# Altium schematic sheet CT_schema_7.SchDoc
size 226 x 144 mm
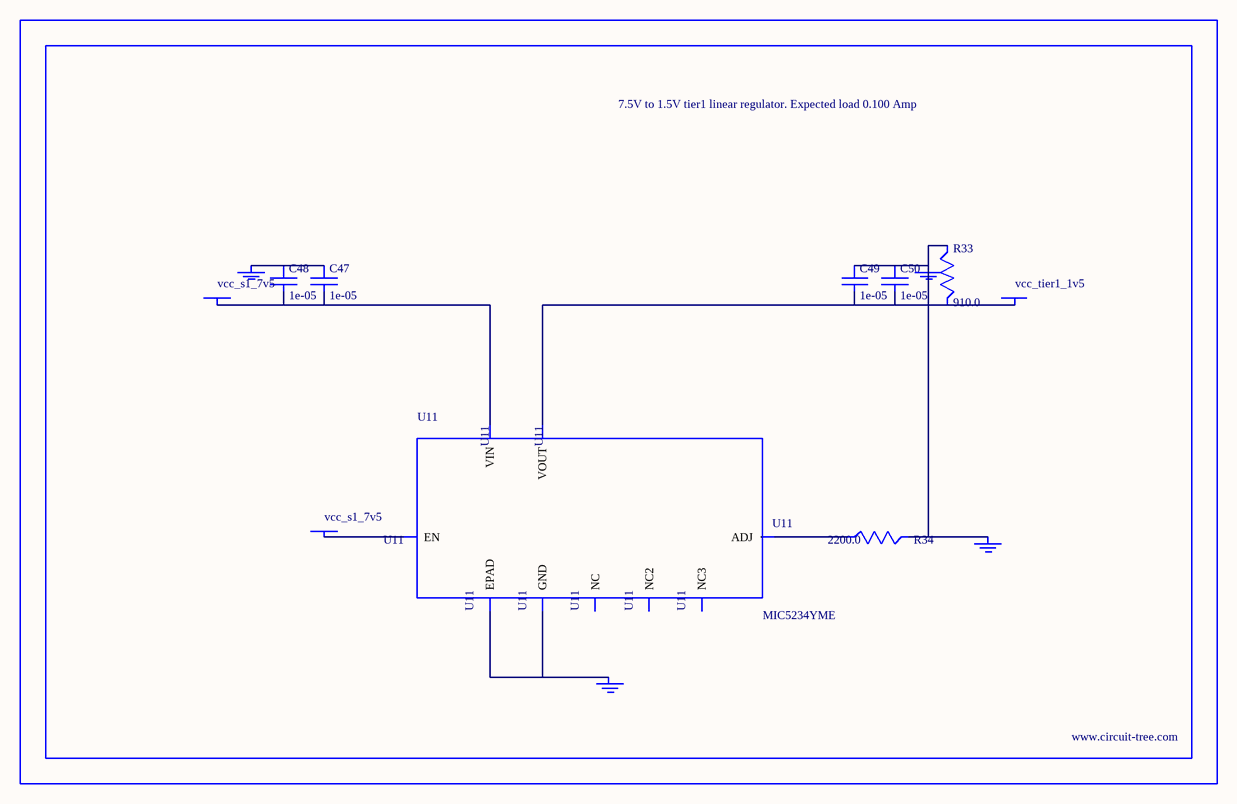
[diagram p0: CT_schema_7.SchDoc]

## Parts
BORDER6  (no value)
C47  1e-05  [C1210]
C48  1e-05  [C1210]
C49  1e-05  [C1210]
C50  1e-05  [C1210]
GND_INSTANCE_6_0  (no value)
GND_INSTANCE_6_1  (no value)
GND_INSTANCE_6_2  (no value)
GND_INSTANCE_6_3  (no value)
POWER_INSTANCE_6_0  vcc_tier1_1v5
POWER_INSTANCE_6_1  vcc_s1_7v5
POWER_INSTANCE_6_2  vcc_s1_7v5
R33  910.0  [R0603]
R34  2200.0  [R0603]
U11  MIC5234YME  [SOIC-8_EP]

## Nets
NetC47_1: C47.1 C48.1 GND_INSTANCE_6_3.0(GND)
NetC47_2: C47.2 C48.2 POWER_INSTANCE_6_2.0(PWR) U11.8(VIN)
NetC49_1: C49.1 C50.1 GND_INSTANCE_6_0.0(GND) GND_INSTANCE_6_1.0(GND) R33.1 R34.2
NetC49_2: C49.2 C50.2 POWER_INSTANCE_6_0.0(PWR) R33.2 U11.1(VOUT)
NetGND_INSTANCE_6_2_0: GND_INSTANCE_6_2.0(GND) U11.7(GND) U11.EPAD
NetPOWER_INSTANCE_6_1_0: POWER_INSTANCE_6_1.0(PWR) U11.5(EN)
NetR34_1: R34.1 U11.4(ADJ)

Not connected (* = marked no-connect by the designer): U11 2(NC) 3(NC2) 6(NC3)

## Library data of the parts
BORDER6 = BORDER_PAGE6
C47-C50 = C1210C106K5PACTU
GND_INSTANCE_6_0-GND_INSTANCE_6_3 = GND
POWER_INSTANCE_6_0-POWER_INSTANCE_6_2 = PWR
R33 = RC0603JR-07910RL
R34 = RC0603JR-072K2L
